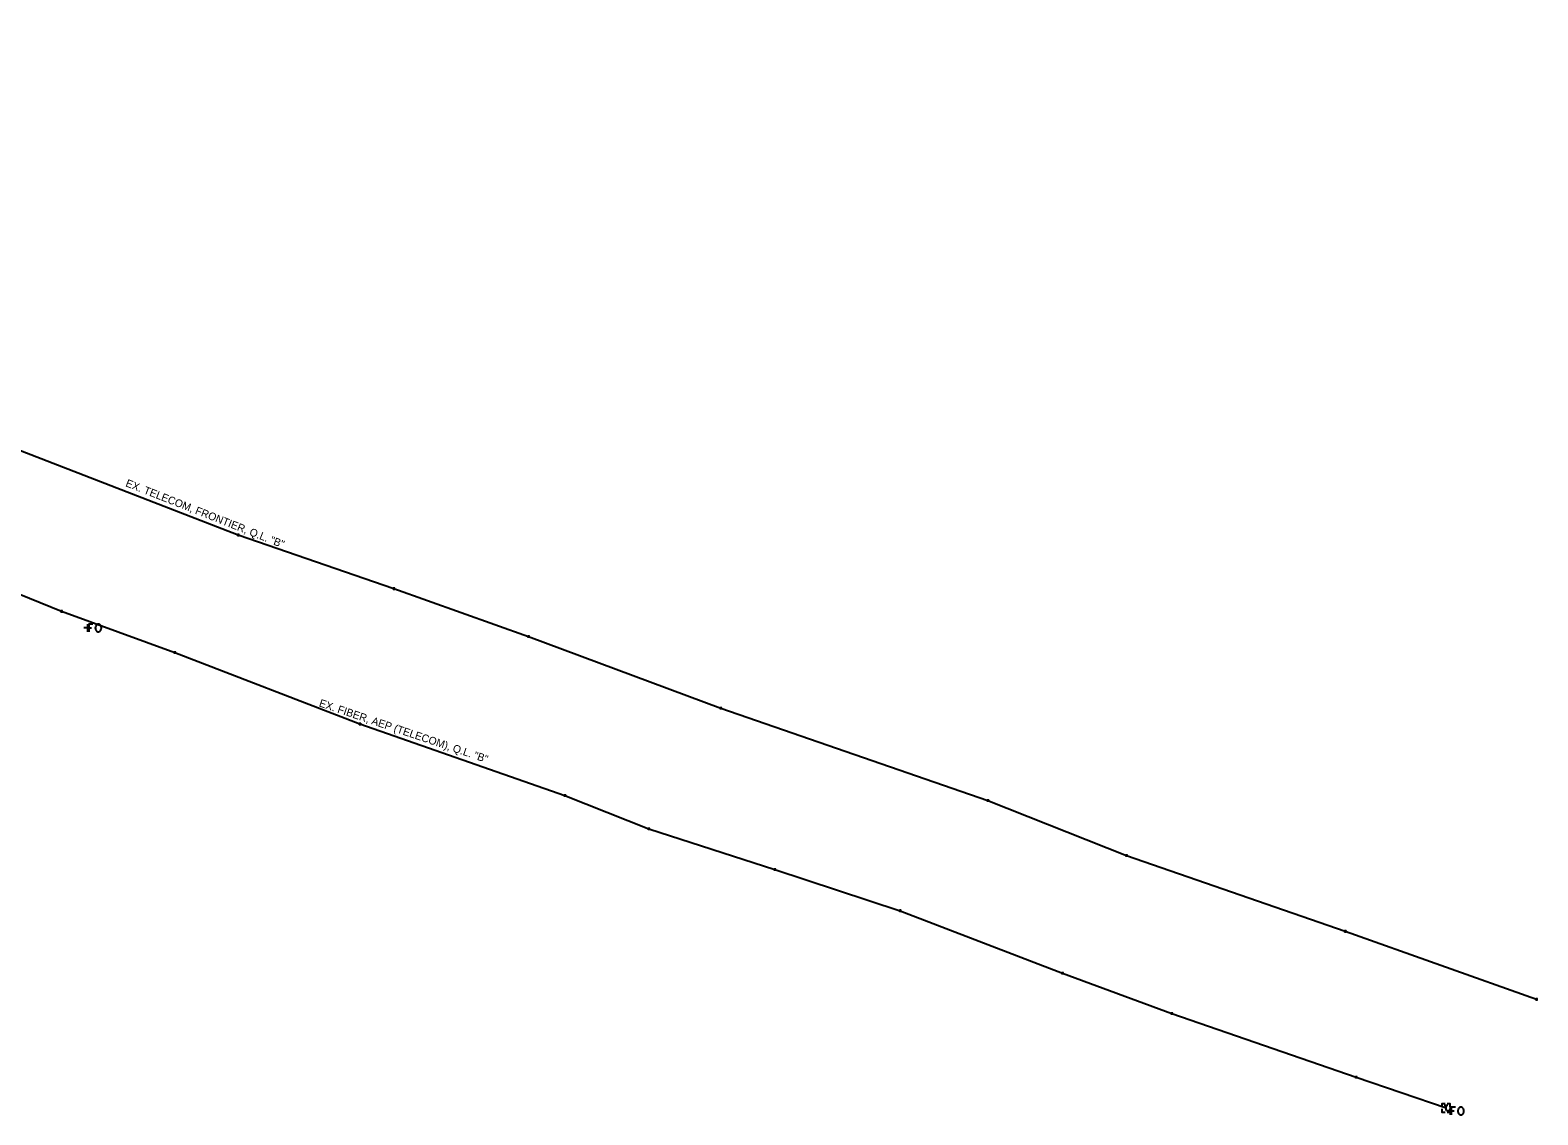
# Model space of a CAD drawing. Extents: x 2046588 to 2048646, y 455919 to 457871.
# Drawn here: x 2048096 to 2048646, y 456615 to 457011 of the extents above; entities that cross this region are included whole.
import ezdxf

# ---------------------------------------------------------------- set-up
doc = ezdxf.new("R2010")
doc.units = 0
for name, color, linetype in [('CM_Corridor_Top_Mesh', 7, 'Continuous'), ('MD_P_Surface_Non-Reinforced_Concrete_Pavement', 7, 'Continuous'), ('UT_P_Gas', 7, 'Continuous'), ('UT_X_Gas', 7, 'Continuous'), ('UT_X_Gas_Text', 7, 'Continuous'), ('UT_X_Overhead_Combined', 7, 'Continuous')]:
    doc.layers.add(name, color=color, linetype=linetype)

msp = doc.modelspace()

# ---------------------------------------------------------------- linework, layer by layer
at = {"layer": 'CM_Corridor_Top_Mesh'}
msp.add_lwpolyline([(2047667.24, 457010.56), (2047697.33, 456993.62), (2047786.8, 456966.6), (2047857.15, 456941.14), (2047942.17, 456911.18), (2048015.15, 456885.28), (2048069.44, 456866.41), (2048172.16, 456826.67), (2048228.9, 456807.13), (2048277.95, 456789.73), (2048347.98, 456763.63), (2048445.37, 456729.99), (2048495.85, 456709.95), (2048575.59, 456682.31), (2048645.25, 456657.54)], dxfattribs=at)
at = {"layer": 'UT_P_Gas'}
for p, q in [((2048611.67, 456618.99), (2048612.97, 456618.99)), ((2048612.32, 456616.99), (2048612.32, 456618.99)), ((2048612.32, 456617.99), (2048612.32, 456617.99))]:
    msp.add_line(p, q, dxfattribs=at)
for points in [[(2048611.92, 456619.49), (2048610.82, 456619.49), (2048610.82, 456618.39)], [(2048610.82, 456617.59), (2048610.82, 456616.49), (2048611.92, 456616.49)], [(2048613.82, 456618.39), (2048613.82, 456619.49), (2048612.72, 456619.49)], [(2048612.72, 456616.49), (2048613.82, 456616.49), (2048613.82, 456617.59)]]:
    msp.add_lwpolyline(points, dxfattribs=at)
at = {"layer": 'UT_X_Gas'}
for p, q in [((2048171.66, 456826.67), (2048172.66, 456826.67)), ((2048172.16, 456827.17), (2048172.16, 456826.17)), ((2048172.16, 456826.67), (2048172.16, 456826.67)), ((2048228.4, 456807.13), (2048229.4, 456807.13)), ((2048228.9, 456807.63), (2048228.9, 456806.63)), ((2048228.9, 456807.13), (2048228.9, 456807.13)), ((2048107.29, 456798.87), (2048108.29, 456798.87)), ((2048107.79, 456799.37), (2048107.79, 456798.37)), ((2048107.79, 456798.87), (2048107.79, 456798.87)), ((2048277.45, 456789.73), (2048278.45, 456789.73)), ((2048277.95, 456790.23), (2048277.95, 456789.23)), ((2048277.95, 456789.73), (2048277.95, 456789.73)), ((2048148.56, 456783.91), (2048149.56, 456783.91)), ((2048149.06, 456784.41), (2048149.06, 456783.41)), ((2048149.06, 456783.91), (2048149.06, 456783.91)), ((2048347.48, 456763.63), (2048348.48, 456763.63)), ((2048347.98, 456764.13), (2048347.98, 456763.13)), ((2048347.98, 456763.63), (2048347.98, 456763.63)), ((2048216.02, 456757.83), (2048217.02, 456757.83)), ((2048216.52, 456758.33), (2048216.52, 456757.33)), ((2048216.52, 456757.83), (2048216.52, 456757.83)), ((2048290.72, 456731.79), (2048291.72, 456731.79)), ((2048291.22, 456732.29), (2048291.22, 456731.29)), ((2048291.22, 456731.79), (2048291.22, 456731.79)), ((2048444.87, 456729.99), (2048445.87, 456729.99)), ((2048445.37, 456730.49), (2048445.37, 456729.49)), ((2048445.37, 456729.99), (2048445.37, 456729.99)), ((2048321.32, 456719.67), (2048322.32, 456719.67)), ((2048321.82, 456720.17), (2048321.82, 456719.17)), ((2048321.82, 456719.67), (2048321.82, 456719.67)), ((2048495.35, 456709.95), (2048496.35, 456709.95)), ((2048495.85, 456710.45), (2048495.85, 456709.45)), ((2048495.85, 456709.95), (2048495.85, 456709.95)), ((2048367.22, 456704.8), (2048368.22, 456704.8)), ((2048367.72, 456705.3), (2048367.72, 456704.3)), ((2048367.72, 456704.8), (2048367.72, 456704.8)), ((2048412.9, 456689.82), (2048413.9, 456689.82)), ((2048413.4, 456690.32), (2048413.4, 456689.32)), ((2048413.4, 456689.82), (2048413.4, 456689.82)), ((2048575.09, 456682.31), (2048576.09, 456682.31)), ((2048575.59, 456682.81), (2048575.59, 456681.81)), ((2048575.59, 456682.31), (2048575.59, 456682.31)), ((2048472.07, 456667.03), (2048473.07, 456667.03)), ((2048472.57, 456667.53), (2048472.57, 456666.53)), ((2048472.57, 456667.03), (2048472.57, 456667.03)), ((2048644.75, 456657.54), (2048645.75, 456657.54)), ((2048645.25, 456658.04), (2048645.25, 456657.04)), ((2048645.25, 456657.54), (2048645.25, 456657.54)), ((2048511.9, 456652.36), (2048512.9, 456652.36)), ((2048512.4, 456652.86), (2048512.4, 456651.86)), ((2048512.4, 456652.36), (2048512.4, 456652.36)), ((2048579, 456629.17), (2048580, 456629.17)), ((2048579.5, 456629.67), (2048579.5, 456628.67)), ((2048579.5, 456629.17), (2048579.5, 456629.17))]:
    msp.add_line(p, q, dxfattribs=at)
at = {"layer": 'UT_X_Gas_Text'}
for p, q in [((2048117.26, 456792.82), (2048115.86, 456792.82)), ((2048117.26, 456794.22), (2048117.26, 456791.42)), ((2048117.66, 456792.86), (2048118.74, 456792.86)), ((2048613.81, 456616.86), (2048612.41, 456616.86)), ((2048613.81, 456618.26), (2048613.81, 456615.46)), ((2048614.21, 456616.9), (2048615.29, 456616.9))]:
    msp.add_line(p, q, dxfattribs=at)
for points in [[(2048119.19, 456794.22), (2048117.66, 456794.22), (2048117.66, 456791.42)], [(2048120.95, 456794.2), (2048120.88, 456794.18), (2048120.82, 456794.16), (2048120.71, 456794.09), (2048120.64, 456794.05), (2048120.53, 456793.96), (2048120.44, 456793.87), (2048120.4, 456793.83), (2048120.33, 456793.74), (2048120.22, 456793.52), (2048120.13, 456793.3), (2048120.09, 456793.1), (2048120.07, 456792.81), (2048120.09, 456792.5), (2048120.16, 456792.28), (2048120.22, 456792.11), (2048120.27, 456792.02), (2048120.33, 456791.91), (2048120.42, 456791.8), (2048120.49, 456791.73), (2048120.55, 456791.67), (2048120.64, 456791.6), (2048120.75, 456791.53), (2048120.95, 456791.45), (2048121.06, 456791.42), (2048121.28, 456791.42), (2048121.37, 456791.45), (2048121.46, 456791.47), (2048121.57, 456791.51), (2048121.68, 456791.58), (2048121.74, 456791.62), (2048121.81, 456791.67), (2048121.88, 456791.73), (2048121.94, 456791.82), (2048121.99, 456791.89), (2048122.03, 456791.95), (2048122.07, 456792.02), (2048122.14, 456792.15), (2048122.21, 456792.31), (2048122.25, 456792.48), (2048122.27, 456792.64), (2048122.27, 456792.66), (2048122.27, 456792.81), (2048122.27, 456792.95), (2048122.25, 456793.12), (2048122.21, 456793.3), (2048122.16, 456793.43), (2048122.1, 456793.59), (2048122.03, 456793.72), (2048121.92, 456793.85), (2048121.83, 456793.94), (2048121.74, 456794.03), (2048121.65, 456794.09), (2048121.52, 456794.16), (2048121.39, 456794.2), (2048121.26, 456794.22), (2048121.1, 456794.22), (2048120.95, 456794.2)], [(2048615.74, 456618.26), (2048614.21, 456618.26), (2048614.21, 456615.46)], [(2048617.5, 456618.24), (2048617.43, 456618.22), (2048617.37, 456618.2), (2048617.26, 456618.13), (2048617.19, 456618.09), (2048617.08, 456618), (2048616.99, 456617.91), (2048616.95, 456617.87), (2048616.88, 456617.78), (2048616.77, 456617.56), (2048616.68, 456617.34), (2048616.64, 456617.14), (2048616.62, 456616.85), (2048616.64, 456616.54), (2048616.71, 456616.32), (2048616.77, 456616.15), (2048616.82, 456616.06), (2048616.88, 456615.95), (2048616.97, 456615.84), (2048617.04, 456615.77), (2048617.1, 456615.71), (2048617.19, 456615.64), (2048617.3, 456615.57), (2048617.5, 456615.49), (2048617.61, 456615.46), (2048617.83, 456615.46), (2048617.92, 456615.49), (2048618.01, 456615.51), (2048618.12, 456615.55), (2048618.23, 456615.62), (2048618.29, 456615.66), (2048618.36, 456615.71), (2048618.42, 456615.77), (2048618.49, 456615.86), (2048618.53, 456615.93), (2048618.58, 456615.99), (2048618.62, 456616.06), (2048618.69, 456616.19), (2048618.76, 456616.35), (2048618.8, 456616.52), (2048618.82, 456616.68), (2048618.82, 456616.7), (2048618.82, 456616.85), (2048618.82, 456616.98), (2048618.8, 456617.16), (2048618.76, 456617.34), (2048618.71, 456617.47), (2048618.65, 456617.62), (2048618.58, 456617.76), (2048618.47, 456617.89), (2048618.38, 456617.98), (2048618.29, 456618.06), (2048618.2, 456618.13), (2048618.07, 456618.2), (2048617.94, 456618.24), (2048617.81, 456618.26), (2048617.65, 456618.26), (2048617.5, 456618.24)]]:
    msp.add_lwpolyline(points, dxfattribs=at)
at = {"layer": 'UT_X_Overhead_Combined'}
msp.add_lwpolyline([(2048064.85, 456816.32), (2048107.79, 456798.87), (2048149.06, 456783.91), (2048216.52, 456757.83), (2048291.22, 456731.79), (2048321.82, 456719.67), (2048367.72, 456704.8), (2048413.4, 456689.82), (2048472.57, 456667.03), (2048512.4, 456652.36), (2048579.5, 456629.17), (2048612.32, 456617.99)], dxfattribs=at)

# ---------------------------------------------------------------- texts
at = {"layer": 'MD_P_Surface_Non-Reinforced_Concrete_Pavement'}
for s, rotation, p in [('EX. TELECOM, FRONTIER, Q.L. "B"', 338.4803, (2048130.86, 456844.49)), ('EX. FIBER, AEP (TELECOM), Q.L. "B"', 341.3334, (2048201.37, 456764.31))]:
    msp.add_text(s, height=2.8, rotation=rotation, dxfattribs=at).set_placement(p)

doc.saveas('drawing.dxf')
